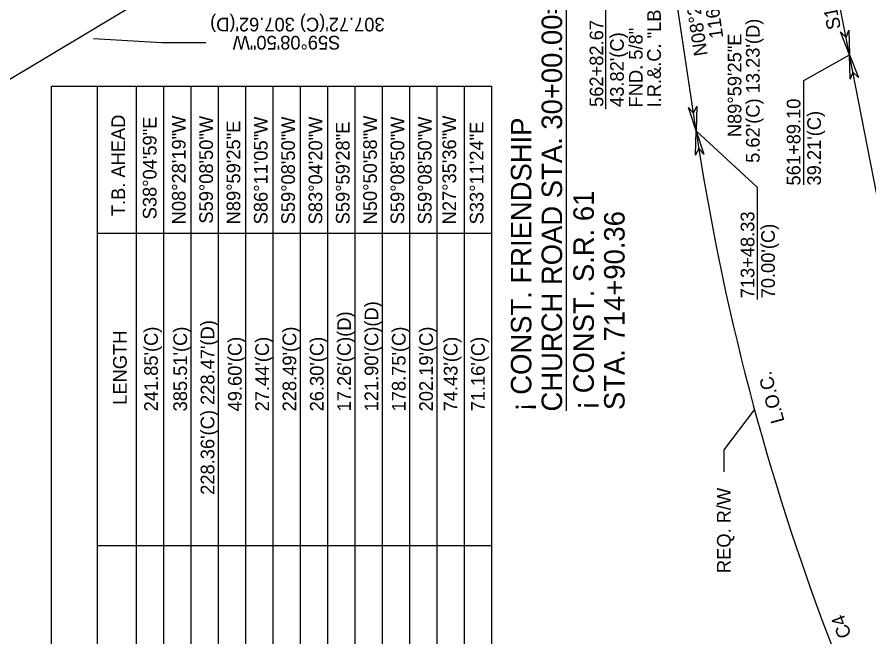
# Model space of a CAD drawing. Extents: x 2003883 to 2008298, y 399149 to 424047.
# Drawn here: x 2005586.8 to 2005898.6, y 403344.2 to 403570.9 of the extents above; entities that cross this region are included whole.
import ezdxf

# ---------------------------------------------------------------- set-up
doc = ezdxf.new("R2010")
doc.units = 0
for name, color, linetype in [('BaselineFlagLT', 7, 'Continuous'), ('BaselineTextWt1', 7, 'Continuous'), ('ConstLimitsText', 7, 'Continuous'), ('DataBoxWt0', 7, 'Continuous'), ('DataBoxWt2', 7, 'Continuous'), ('MonText', 7, 'Continuous'), ('RWandLA_Text', 7, 'Continuous'), ('RWandLA_Text_ep', 7, 'Continuous'), ('RWLine', 7, 'Continuous'), ('RWLine_ep', 7, 'Continuous'), ('TextMisc', 7, 'Continuous')]:
    doc.layers.add(name, color=color, linetype=linetype)

msp = doc.modelspace()

# ---------------------------------------------------------------- linework, layer by layer
at = {"layer": 'BaselineFlagLT'}
msp.add_lwpolyline([(2005883.62, 403680.16), (2005787.78, 403620.36), (2005787.78, 403426.95)], dxfattribs=at)
at = {"layer": 'DataBoxWt0'}
for p, q in [((2005740.53, 403070.91), (2005740.53, 403545.63)), ((2005750.53, 403070.91), (2005750.53, 403545.63)), ((2005616.26, 403491.89), (2005760.53, 403491.89)), ((2005616.26, 403377.62), (2005760.53, 403377.62))]:
    msp.add_line(p, q, dxfattribs=at)
for points in [[(2005630.53, 403070.91), (2005630.53, 403545.63)], [(2005640.53, 403070.91), (2005640.53, 403545.63)], [(2005650.53, 403070.91), (2005650.53, 403545.63)], [(2005660.53, 403070.91), (2005660.53, 403545.63)], [(2005670.53, 403070.91), (2005670.53, 403545.63)], [(2005680.53, 403070.91), (2005680.53, 403545.63)], [(2005690.53, 403070.91), (2005690.53, 403545.63)], [(2005700.53, 403070.91), (2005700.53, 403545.63)], [(2005710.53, 403070.91), (2005710.53, 403545.63)], [(2005720.53, 403070.91), (2005720.53, 403545.63)], [(2005730.53, 403070.91), (2005730.53, 403545.63)], [(2005740.53, 403070.91), (2005740.53, 403545.63)], [(2005740.53, 403070.91), (2005740.53, 403545.63)]]:
    msp.add_lwpolyline(points, dxfattribs=at)
at = {"layer": 'DataBoxWt2'}
for p, q in [((2005599.36, 403070.91), (2005599.36, 403545.63)), ((2005599.36, 403545.63), (2005760.53, 403545.63)), ((2005616.26, 403491.89), (2005616.26, 403545.63)), ((2005760.53, 403070.91), (2005760.53, 403545.63)), ((2005616.26, 403377.62), (2005616.26, 403491.89)), ((2005616.26, 403263.35), (2005616.26, 403377.62))]:
    msp.add_line(p, q, dxfattribs=at)
at = {"layer": 'RWandLA_Text'}
for p, q in [((2005834.36, 403535.74), (2005835.54, 403538.34)), ((2005835.54, 403538.34), (2005835.31, 403529.36)), ((2005835.31, 403529.36), (2005832.47, 403537.89)), ((2005832.47, 403537.89), (2005834.36, 403535.74)), ((2005835.08, 403520.38), (2005835.31, 403529.36)), ((2005835.31, 403529.36), (2005838.15, 403520.84)), ((2005836.26, 403522.98), (2005835.08, 403520.38)), ((2005838.15, 403520.84), (2005836.26, 403522.98))]:
    msp.add_line(p, q, dxfattribs=at)
for points in [[(2005857.79, 403467.69), (2005857.79, 403508.57), (2005835.31, 403529.36)], [(2005845.61, 403404.57), (2005845.61, 403412.7), (2005856.7, 403427.27)]]:
    msp.add_lwpolyline(points, dxfattribs=at)
at = {"layer": 'RWandLA_Text_ep'}
for p, q in [((2005891.47, 403557.16), (2005888.2, 403565.53)), ((2005888.2, 403565.53), (2005890.19, 403563.49)), ((2005890.19, 403563.49), (2005891.24, 403566.15)), ((2005891.24, 403566.15), (2005891.47, 403557.16)), ((2005891.64, 403548.18), (2005891.47, 403557.16)), ((2005891.47, 403557.16), (2005894.68, 403548.77)), ((2005892.7, 403550.83), (2005891.64, 403548.18)), ((2005894.68, 403548.77), (2005892.7, 403550.83))]:
    msp.add_line(p, q, dxfattribs=at)
for points in [[(2005802.32, 403537.28), (2005802.32, 403591.36), (2005866.19, 403646.34)], [(2005655.82, 403561.56), (2005639.66, 403561.56), (2005614.78, 403562.94)], [(2005874.69, 403509.6), (2005874.69, 403547.75), (2005891.47, 403557.16)]]:
    msp.add_lwpolyline(points, dxfattribs=at)
at = {"layer": 'RWLine'}
msp.add_line((2005835.31, 403529.36), (2005818.11, 403644.85), dxfattribs=at)
msp.add_arc((2006714.61, 403660.33), 889, 188.4719, 213.31785, dxfattribs=at)
at = {"layer": 'RWLine_ep'}
for p, q in [((2005891.47, 403557.16), (2005873.22, 403647.73)), ((2005385.95, 403429.92), (2005650.12, 403587.73)), ((2005930.91, 403354.34), (2005891.47, 403557.16))]:
    msp.add_line(p, q, dxfattribs=at)

# ---------------------------------------------------------------- texts
at = {"layer": 'BaselineTextWt1'}
for s, rotation, p in [('¡ CONST. S.R. 61', 98.4719, (2005913.84, 403546.21)), ('CHURCH ROAD STA. 30+00.00=', 90, (2005786.26, 403426.66)), ('¡ CONST. FRIENDSHIP', 90, (2005775.01, 403426.66)), ('¡ CONST. S.R. 61', 90, (2005797.88, 403427.2)), ('STA. 714+90.36', 90, (2005809.13, 403427.2))]:
    msp.add_text(s, height=7.5, rotation=rotation, dxfattribs=at).set_placement(p)
at = {"layer": 'ConstLimitsText'}
msp.add_text('L.O.C.', height=5, rotation=105.0008, dxfattribs=at).set_placement((2005867.7, 403423.08))
at = {"layer": 'MonText'}
for s, p in [('I.R.&.C. "LB 7160"', (2005822.4, 403537.88)), ('FND. 5/8"', (2005815.72, 403537.88))]:
    msp.add_text(s, height=5, rotation=90, dxfattribs=at).set_placement(p)
at = {"layer": 'RWandLA_Text'}
for s, rotation, p in [('N08°28\'19"W', 98.4719, (2005839.55, 403557.05)), ("116.76'(C)", 98.4719, (2005845.3, 403563.45)), ('713+48.33', 90, (2005856.62, 403468.04)), ("70.00'(C)", 90, (2005864.12, 403468.04)), ('REQ. R/W', 90, (2005847.95, 403367.56)), ('C4', 110.689, (2005892.25, 403344.82))]:
    msp.add_text(s, height=5, rotation=rotation, dxfattribs=at).set_placement(p)
at = {"layer": 'RWandLA_Text_ep'}
for s, rotation, p in [('S11°23\'38"E', 101.3939, (2005888.34, 403566.88)), ("307.72'(C) 307.62'(D)", 180, (2005721.31, 403570.69)), ('562+82.67', 90, (2005801.34, 403538.06)), ("5.62'(C) 13.23'(D)", 90, (2005858.56, 403517.61)), ('S59°08\'50"W', 180, (2005705.1, 403564.06)), ("43.82'(C)", 90, (2005808.84, 403538.06)), ('N89°59\'25"E', 90, (2005851.88, 403527)), ('561+89.10', 90, (2005873.48, 403509.32)), ("39.21'(C)", 90, (2005880.98, 403509.32))]:
    msp.add_text(s, height=5, rotation=rotation, dxfattribs=at).set_placement(p)
at = {"layer": 'TextMisc'}
for s, p in [('T.B. AHEAD', (2005626.31, 403498.09)), ('S38°04\'59"E', (2005637.82, 403496.96)), ('N08°28\'19"W', (2005648.48, 403495.11)), ('S59°08\'50"W', (2005658.48, 403495.37)), ('N89°59\'25"E', (2005668.48, 403495.11)), ('S86°11\'05"W', (2005678.48, 403495.11)), ('S59°08\'50"W', (2005688.48, 403495.11)), ('S83°04\'20"W', (2005698.48, 403495.11)), ('S59°59\'28"E', (2005708.48, 403495.11)), ('N50°50\'58"W', (2005718.48, 403495.11)), ('S59°08\'50"W', (2005728.48, 403495.11)), ('S59°08\'50"W', (2005738.48, 403495.11)), ('N27°35\'36"W', (2005747.48, 403495.11)), ('S33°11\'24"E', (2005757.48, 403495.11)), ("121.90'(C)(D)", (2005718.98, 403426.7)), ("17.26'(C)(D)", (2005708.98, 403426.7)), ("241.85'(C)", (2005638.31, 403426.7)), ("385.51'(C)", (2005648.98, 403426.7)), ("228.36'(C) 228.47'(D)", (2005658.98, 403396.2)), ("228.49'(C)", (2005688.98, 403426.7)), ("178.75'(C)", (2005728.98, 403426.7)), ("202.19'(C)", (2005738.98, 403426.7)), ('LENGTH', (2005626.92, 403429.13)), ("49.60'(C)", (2005668.98, 403426.7)), ("27.44'(C)", (2005678.98, 403426.7)), ("26.30'(C)", (2005698.98, 403426.7)), ("74.43'(C)", (2005747.97, 403426.7)), ("71.16'(C)", (2005757.97, 403426.7))]:
    msp.add_text(s, height=5, rotation=90, dxfattribs=at).set_placement(p)

doc.saveas('drawing.dxf')
